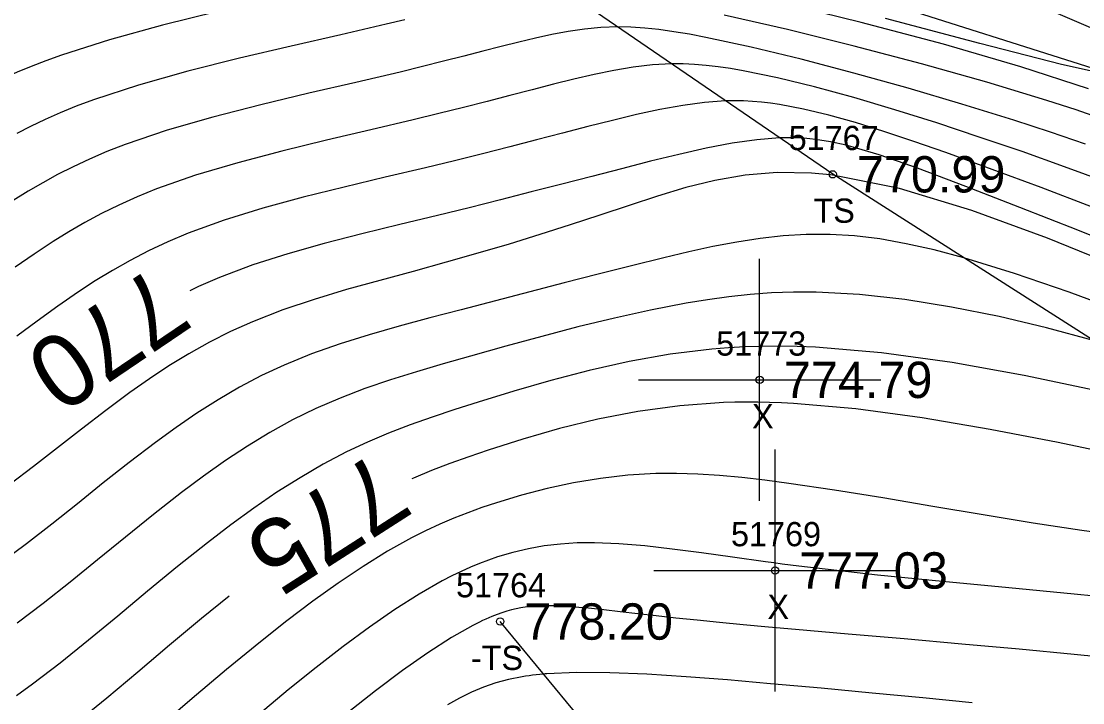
# Model space of a CAD drawing. Extents: x 1378535 to 1380697, y 997729 to 1000024.
# Drawn here: x 1379706.1 to 1379749.94, y 998840.44 to 998868.57 of the extents above; entities that cross this region are included whole.
import ezdxf

# ---------------------------------------------------------------- set-up
doc = ezdxf.new("R2010")
doc.units = 0
for name, color, linetype in [('RD_DTM_BkLn2', 7, 'Continuous'), ('RD_DTM_BkLn_txCode', 7, 'Continuous'), ('RD_DTM_Major1', 7, 'Continuous'), ('RD_DTM_Major1_Lbl', 7, 'Continuous'), ('RD_DTM_Minor1', 7, 'Continuous'), ('RD_EX_H2O', 7, 'Continuous'), ('RD_EX_Misc', 7, 'Continuous'), ('RD_EX_Misc_txCode', 7, 'Continuous'), ('RD_EX_TX_Misc_ELEV', 7, 'Continuous'), ('RD_SMD_Locator', 7, 'Continuous')]:
    doc.layers.add(name, color=color, linetype=linetype)

msp = doc.modelspace()

# ---------------------------------------------------------------- linework, layer by layer
at = {"layer": 'RD_DTM_BkLn2'}
for points in [[(1379768.924, 998848.169), (1379761.558, 998848.269), (1379739.614, 998862.253), (1379721.666, 998874.547)], [(1380321.815, 998326.615), (1380322.659, 998329.174), (1380322.261, 998332.77), (1380321.137, 998334.343), (1380320.107, 998334.637), (1380319.184, 998334.516), (1380315.041, 998338.979), (1380309.473, 998346.954), (1380304.757, 998357.874), (1380262.267, 998407.427), (1380207.067, 998458.846), (1380160.069, 998502.831), (1380114.551, 998544.043), (1380071.667, 998582.108), (1380029.128, 998620.782), (1379985.006, 998662.48), (1379936.375, 998704.347), (1379893.878, 998744.802), (1379846.871, 998787.948), (1379800.334, 998830.073), (1379753.878, 998865.5), (1379725.58, 998874.504)], [(1379855.611, 998702.628), (1379815.746, 998738.674), (1379770.168, 998788.836), (1379745.983, 998819.459), (1379725.877, 998843.791)]]:
    msp.add_lwpolyline(points, dxfattribs=at)
at = {"layer": 'RD_DTM_Major1'}
for points in [[(1379750.184, 998865.782), (1379747.386, 998866.697), (1379744.191, 998867.624), (1379740.79, 998868.526), (1379737.37, 998869.365)], [(1379714.218, 998868.979), (1379711.934, 998868.409), (1379709.745, 998867.806), (1379707.761, 998867.176), (1379707.116, 998866.943), (1379706.507, 998866.708), (1379705.931, 998866.47), (1379705.384, 998866.228), (1379704.86, 998865.983), (1379704.357, 998865.734), (1379703.744, 998865.413), (1379703.148, 998865.087), (1379702.561, 998864.756), (1379702.351, 998864.636)], [(1379752.196, 998858.954), (1379749.737, 998859.942), (1379747.344, 998860.89), (1379745.106, 998861.756), (1379743.114, 998862.501), (1379742.295, 998862.794), (1379741.537, 998863.051), (1379740.83, 998863.27), (1379740.163, 998863.451), (1379739.526, 998863.592), (1379738.907, 998863.692), (1379738.664, 998863.72), (1379738.421, 998863.741), (1379738.176, 998863.756), (1379737.928, 998863.764), (1379737.676, 998863.764), (1379737.417, 998863.758), (1379736.478, 998863.682), (1379735.464, 998863.535), (1379734.387, 998863.328), (1379733.259, 998863.076), (1379732.091, 998862.791), (1379730.895, 998862.486), (1379729.667, 998862.169), (1379728.424, 998861.848), (1379727.165, 998861.524), (1379725.891, 998861.199), (1379724.602, 998860.876), (1379723.298, 998860.556), (1379721.731, 998860.179), (1379720.163, 998859.798), (1379718.615, 998859.401), (1379717.107, 998858.977), (1379715.659, 998858.514), (1379714.29, 998858), (1379713.417, 998857.619), (1379713.063, 998857.446)], [(1379751.669, 998850.604), (1379748.929, 998851.176), (1379746.116, 998851.72), (1379743.305, 998852.198), (1379740.572, 998852.569), (1379737.992, 998852.795), (1379737.492, 998852.82), (1379737.001, 998852.837), (1379736.517, 998852.846), (1379736.04, 998852.848), (1379735.569, 998852.841), (1379735.103, 998852.827), (1379733.304, 998852.696), (1379731.572, 998852.46), (1379729.91, 998852.14), (1379728.324, 998851.755), (1379726.815, 998851.326), (1379725.389, 998850.871), (1379724.583, 998850.595), (1379723.802, 998850.313), (1379723.041, 998850.019), (1379722.296, 998849.707), (1379722.237, 998849.68)], [(1379714.682, 998844.839), (1379713.547, 998843.916), (1379712.228, 998842.812), (1379710.917, 998841.705), (1379709.631, 998840.626), (1379708.388, 998839.608), (1379707.204, 998838.685), (1379706.583, 998838.226), (1379705.98, 998837.8)]]:
    msp.add_lwpolyline(points, dxfattribs=at)
at = {"layer": 'RD_DTM_Minor1'}
for points in [[(1379750.801, 998864.523), (1379749.666, 998864.916), (1379748.453, 998865.307), (1379745.975, 998866.054), (1379743.284, 998866.81), (1379740.499, 998867.544), (1379737.741, 998868.227), (1379735.128, 998868.828)], [(1379750.059, 998863.499), (1379748.612, 998863.99), (1379747.094, 998864.483), (1379744.951, 998865.149), (1379742.728, 998865.808), (1379740.493, 998866.435), (1379738.311, 998867.009), (1379736.25, 998867.508), (1379734.375, 998867.908), (1379733.695, 998868.035), (1379733.05, 998868.141), (1379732.436, 998868.226), (1379731.848, 998868.287), (1379731.282, 998868.324), (1379730.734, 998868.336), (1379730.042, 998868.312), (1379729.364, 998868.248), (1379728.693, 998868.151), (1379728.02, 998868.024), (1379727.34, 998867.875), (1379726.644, 998867.708), (1379725.917, 998867.527), (1379725.162, 998867.334), (1379724.373, 998867.132), (1379723.545, 998866.92), (1379722.672, 998866.702), (1379721.749, 998866.477), (1379719.925, 998866.05), (1379717.984, 998865.601), (1379715.991, 998865.125), (1379714.016, 998864.617), (1379712.125, 998864.071), (1379710.385, 998863.484), (1379709.629, 998863.189), (1379708.916, 998862.883), (1379708.242, 998862.567), (1379707.6, 998862.241), (1379706.985, 998861.904), (1379706.391, 998861.558), (1379705.661, 998861.106)], [(1379721.949, 998868.636), (1379721.178, 998868.451), (1379719.302, 998868.016), (1379717.253, 998867.548), (1379715.118, 998867.044), (1379712.985, 998866.506), (1379710.943, 998865.933), (1379709.079, 998865.324), (1379708.374, 998865.06), (1379707.71, 998864.789), (1379707.083, 998864.512), (1379706.486, 998864.229), (1379705.917, 998863.939)], [(1379751.616, 998866.22), (1379749.066, 998866.791), (1379745.69, 998867.648), (1379741.801, 998868.683)], [(1379750.917, 998861.933), (1379749.189, 998862.568), (1379747.436, 998863.189), (1379745.669, 998863.793), (1379743.911, 998864.373), (1379742.175, 998864.92), (1379740.483, 998865.421), (1379738.861, 998865.865), (1379737.331, 998866.238), (1379735.917, 998866.529), (1379735.391, 998866.619), (1379734.884, 998866.692), (1379734.391, 998866.749), (1379733.909, 998866.789), (1379733.434, 998866.809), (1379732.961, 998866.81), (1379732.172, 998866.767), (1379731.378, 998866.675), (1379730.575, 998866.542), (1379729.759, 998866.374), (1379728.928, 998866.181), (1379728.078, 998865.969), (1379727.195, 998865.743), (1379726.285, 998865.507), (1379725.343, 998865.264), (1379724.365, 998865.014), (1379723.348, 998864.759), (1379722.286, 998864.5), (1379720.532, 998864.088), (1379718.708, 998863.662), (1379716.863, 998863.213), (1379715.045, 998862.734), (1379713.303, 998862.217), (1379711.687, 998861.652), (1379710.887, 998861.327), (1379710.131, 998860.986), (1379709.413, 998860.631), (1379708.726, 998860.26), (1379708.065, 998859.876), (1379707.424, 998859.478), (1379706.632, 998858.956), (1379705.854, 998858.42)], [(1379750.3, 998860.914), (1379748.227, 998861.703), (1379746.205, 998862.454), (1379744.28, 998863.149), (1379742.97, 998863.607), (1379741.731, 998864.021), (1379740.559, 998864.386), (1379739.453, 998864.697), (1379738.408, 998864.948), (1379737.421, 998865.134), (1379737.043, 998865.189), (1379736.672, 998865.233), (1379736.303, 998865.265), (1379735.935, 998865.284), (1379735.565, 998865.291), (1379735.189, 998865.284), (1379734.322, 998865.22), (1379733.417, 998865.098), (1379732.48, 998864.927), (1379731.513, 998864.717), (1379730.518, 998864.478), (1379729.501, 998864.221), (1379728.45, 998863.951), (1379727.375, 998863.673), (1379726.276, 998863.39), (1379725.148, 998863.103), (1379723.991, 998862.814), (1379722.802, 998862.525), (1379721.133, 998862.13), (1379719.434, 998861.728), (1379717.737, 998861.306), (1379716.075, 998860.855), (1379714.481, 998860.365), (1379712.989, 998859.825), (1379712.15, 998859.471), (1379711.354, 998859.096), (1379710.593, 998858.701), (1379709.862, 998858.286), (1379709.155, 998857.853), (1379708.465, 998857.401), (1379707.607, 998856.807), (1379706.761, 998856.195), (1379705.922, 998855.575)], [(1379751.642, 998858.342), (1379748.483, 998859.623), (1379745.353, 998860.764), (1379742.379, 998861.661), (1379739.689, 998862.205), (1379739.526, 998862.226), (1379739.364, 998862.245), (1379739.205, 998862.262), (1379739.046, 998862.277), (1379738.89, 998862.291), (1379738.734, 998862.302), (1379737.314, 998862.328), (1379735.993, 998862.219), (1379734.745, 998862.003), (1379733.547, 998861.703), (1379732.375, 998861.348), (1379731.203, 998860.963), (1379729.996, 998860.564), (1379728.766, 998860.165), (1379727.515, 998859.768), (1379726.245, 998859.376), (1379724.958, 998858.993), (1379723.655, 998858.622), (1379722.28, 998858.247), (1379720.903, 998857.876), (1379719.539, 998857.495), (1379718.199, 998857.092), (1379716.899, 998856.653), (1379715.651, 998856.167), (1379714.746, 998855.76), (1379713.873, 998855.319), (1379713.026, 998854.846), (1379712.201, 998854.342), (1379711.391, 998853.81), (1379710.591, 998853.249), (1379709.587, 998852.506), (1379708.588, 998851.737), (1379707.597, 998850.96), (1379706.612, 998850.192), (1379705.635, 998849.449)], [(1379751.716, 998856.527), (1379749.374, 998857.382), (1379747.124, 998858.154), (1379745.033, 998858.8), (1379743.803, 998859.129), (1379742.651, 998859.39), (1379741.562, 998859.583), (1379740.52, 998859.712), (1379739.511, 998859.775), (1379738.52, 998859.775), (1379737.568, 998859.718), (1379736.613, 998859.61), (1379735.648, 998859.458), (1379734.668, 998859.269), (1379733.666, 998859.05), (1379732.637, 998858.808), (1379731.304, 998858.481), (1379729.93, 998858.134), (1379728.527, 998857.772), (1379727.108, 998857.402), (1379724.263, 998856.658), (1379722.979, 998856.323), (1379721.715, 998855.985), (1379720.476, 998855.632), (1379719.267, 998855.254), (1379718.094, 998854.84), (1379716.96, 998854.38), (1379716.023, 998853.941), (1379715.113, 998853.463), (1379714.226, 998852.946), (1379713.355, 998852.393), (1379712.495, 998851.806), (1379711.641, 998851.186), (1379710.562, 998850.362), (1379709.487, 998849.51), (1379708.42, 998848.651), (1379707.363, 998847.805), (1379706.32, 998846.992), (1379705.296, 998846.235)], [(1379750.378, 998855.394), (1379748.444, 998855.915), (1379746.483, 998856.38), (1379744.523, 998856.773), (1379742.592, 998857.082), (1379740.719, 998857.292), (1379738.931, 998857.39), (1379737.997, 998857.392), (1379737.088, 998857.358), (1379736.199, 998857.293), (1379735.321, 998857.198), (1379734.445, 998857.077), (1379733.565, 998856.931), (1379732.092, 998856.647), (1379730.597, 998856.316), (1379729.094, 998855.95), (1379727.594, 998855.56), (1379726.111, 998855.156), (1379724.656, 998854.749), (1379723.527, 998854.429), (1379722.424, 998854.105), (1379721.346, 998853.767), (1379720.294, 998853.407), (1379719.266, 998853.015), (1379718.264, 998852.581), (1379717.307, 998852.111), (1379716.37, 998851.595), (1379715.446, 998851.035), (1379714.532, 998850.434), (1379713.622, 998849.793), (1379712.712, 998849.115), (1379711.556, 998848.211), (1379710.4, 998847.277), (1379709.252, 998846.336), (1379708.119, 998845.412), (1379707.01, 998844.532), (1379705.932, 998843.719)], [(1379750.463, 998853.326), (1379747.527, 998853.946), (1379744.542, 998854.478), (1379741.628, 998854.882), (1379738.901, 998855.114), (1379738.142, 998855.144), (1379737.406, 998855.156), (1379736.691, 998855.151), (1379735.992, 998855.128), (1379735.305, 998855.089), (1379734.628, 998855.034), (1379732.894, 998854.822), (1379731.204, 998854.525), (1379729.561, 998854.16), (1379727.97, 998853.748), (1379726.438, 998853.306), (1379724.97, 998852.852), (1379724.007, 998852.544), (1379723.073, 998852.232), (1379722.162, 998851.907), (1379721.272, 998851.564), (1379720.398, 998851.194), (1379719.536, 998850.79), (1379718.572, 998850.285), (1379717.615, 998849.729), (1379716.662, 998849.125), (1379715.709, 998848.474), (1379714.751, 998847.779), (1379713.787, 998847.042), (1379712.555, 998846.059), (1379711.318, 998845.041), (1379710.088, 998844.018), (1379708.879, 998843.017), (1379707.702, 998842.069), (1379706.57, 998841.201), (1379705.902, 998840.719)], [(1379751.443, 998847.344), (1379749.902, 998847.553), (1379747.895, 998847.856), (1379745.828, 998848.192), (1379743.744, 998848.544), (1379741.684, 998848.891), (1379739.689, 998849.214), (1379737.803, 998849.495), (1379736.808, 998849.627), (1379735.854, 998849.737), (1379734.933, 998849.821), (1379734.04, 998849.878), (1379733.167, 998849.904), (1379732.309, 998849.896), (1379731.156, 998849.829), (1379730.021, 998849.7), (1379728.907, 998849.516), (1379727.817, 998849.284), (1379726.755, 998849.008), (1379725.724, 998848.696), (1379725.128, 998848.496), (1379724.541, 998848.282), (1379723.96, 998848.053), (1379723.381, 998847.804), (1379722.802, 998847.534), (1379722.219, 998847.24), (1379721.228, 998846.689), (1379720.217, 998846.067), (1379719.187, 998845.379), (1379718.138, 998844.629), (1379717.068, 998843.82), (1379715.979, 998842.959), (1379714.577, 998841.805), (1379713.165, 998840.61), (1379711.763, 998839.413)], [(1379752.111, 998844.673), (1379749.582, 998844.925), (1379746.891, 998845.181), (1379744.146, 998845.443), (1379741.46, 998845.711), (1379738.943, 998845.989), (1379738.578, 998846.032), (1379738.22, 998846.076), (1379737.868, 998846.12), (1379737.521, 998846.164), (1379737.18, 998846.209), (1379736.844, 998846.253), (1379735.479, 998846.442), (1379734.196, 998846.622), (1379732.99, 998846.783), (1379731.856, 998846.914), (1379730.787, 998847.005), (1379729.778, 998847.044), (1379729.062, 998847.034), (1379728.372, 998846.989), (1379727.703, 998846.909), (1379727.05, 998846.794), (1379726.409, 998846.643), (1379725.775, 998846.457), (1379725.401, 998846.329), (1379725.027, 998846.188), (1379724.649, 998846.032), (1379724.268, 998845.861), (1379723.882, 998845.674), (1379723.487, 998845.47), (1379722.529, 998844.922), (1379721.525, 998844.284), (1379720.478, 998843.561), (1379719.393, 998842.762), (1379718.274, 998841.894), (1379717.124, 998840.965), (1379715.636, 998839.719)], [(1379751.684, 998842.219), (1379749.589, 998842.434), (1379747.317, 998842.649), (1379744.949, 998842.862), (1379742.565, 998843.07), (1379740.247, 998843.271), (1379738.075, 998843.461), (1379736.965, 998843.561), (1379735.92, 998843.658), (1379734.937, 998843.751), (1379734.012, 998843.843), (1379733.141, 998843.934), (1379732.321, 998844.023), (1379731.559, 998844.111), (1379730.84, 998844.194), (1379730.163, 998844.271), (1379729.527, 998844.337), (1379728.929, 998844.39), (1379728.368, 998844.425), (1379728.081, 998844.436), (1379727.802, 998844.439), (1379727.53, 998844.433), (1379727.262, 998844.418), (1379726.997, 998844.391), (1379726.734, 998844.352), (1379726.542, 998844.315), (1379726.348, 998844.27), (1379726.153, 998844.217), (1379725.954, 998844.155), (1379725.75, 998844.083), (1379725.542, 998844.002), (1379725.416, 998843.949), (1379725.287, 998843.893), (1379725.156, 998843.833), (1379725.023, 998843.769), (1379724.887, 998843.701), (1379724.748, 998843.629), (1379723.869, 998843.127), (1379722.898, 998842.501), (1379721.848, 998841.763), (1379720.731, 998840.927), (1379719.558, 998840.004)], [(1379745.371, 998840.429), (1379743.33, 998840.634), (1379741.241, 998840.837), (1379739.135, 998841.035), (1379737.044, 998841.225), (1379735.271, 998841.379), (1379733.559, 998841.513), (1379731.931, 998841.617), (1379730.413, 998841.679), (1379729.029, 998841.689), (1379727.803, 998841.634), (1379727.78, 998841.632), (1379727.758, 998841.63), (1379727.736, 998841.628), (1379727.691, 998841.624), (1379727.669, 998841.623), (1379727.515, 998841.608), (1379727.364, 998841.592), (1379727.216, 998841.574), (1379727.071, 998841.555), (1379726.929, 998841.534), (1379726.79, 998841.511), (1379726.229, 998841.398), (1379725.698, 998841.255), (1379725.189, 998841.079), (1379724.693, 998840.87), (1379724.199, 998840.626), (1379723.701, 998840.345)]]:
    msp.add_lwpolyline(points, dxfattribs=at)
at = {"layer": 'RD_EX_H2O'}
msp.add_lwpolyline([(1379736.894, 998874.065), (1379751.828, 998867.642), (1379771.891, 998856.367), (1379801.405, 998830.336), (1379847.091, 998789.131), (1379893.404, 998746.574), (1379936.347, 998705.935), (1379983.745, 998664.271), (1380032.204, 998621.669), (1380073.465, 998582.905), (1380116.04, 998544.611), (1380160.954, 998503.902), (1380207.715, 998459.994), (1380261.249, 998409.341)], dxfattribs=at)
at = {"layer": 'RD_EX_Misc'}
for p, q in [((1379736.597, 998848.768), (1379736.597, 998858.768)), ((1379731.597, 998853.768), (1379741.597, 998853.768)), ((1379737.232, 998840.899), (1379737.232, 998850.899)), ((1379732.232, 998845.899), (1379742.232, 998845.899))]:
    msp.add_line(p, q, dxfattribs=at)
at = {"layer": 'RD_SMD_Locator'}
for centre in [(1379739.614, 998862.253), (1379736.597, 998853.768), (1379737.232, 998845.899), (1379725.877, 998843.791)]:
    msp.add_circle(centre, 0.15, dxfattribs=at)

# ---------------------------------------------------------------- texts
at = {"layer": 'RD_DTM_BkLn_txCode'}
for s, p in [('51767', (1379737.795, 998863.253)), ('TS', (1379738.819, 998860.253)), ('51764', (1379724.058, 998844.791)), ('-TS', (1379724.672, 998841.791))]:
    msp.add_text(s, height=1, dxfattribs=at).set_placement(p)
at = {"layer": 'RD_DTM_Major1_Lbl'}
for s, rotation, p in [('770', 214.0889, (1379711.608, 998858.543)), ('775', 212.6523, (1379720.776, 998850.873))]:
    msp.add_text(s, height=3, rotation=rotation, dxfattribs=at).set_placement(p)
at = {"layer": 'RD_EX_Misc_txCode'}
for s, p in [('51773', (1379734.802, 998854.768)), ('X', (1379736.282, 998851.768)), ('51769', (1379735.413, 998846.899)), ('X', (1379736.917, 998843.899))]:
    msp.add_text(s, height=1, dxfattribs=at).set_placement(p)
at = {"layer": 'RD_EX_TX_Misc_ELEV'}
for s, p in [('770.99', (1379740.614, 998861.503)), ('774.79', (1379737.597, 998853.018)), ('777.03', (1379738.232, 998845.149)), ('778.20', (1379726.877, 998843.041))]:
    msp.add_text(s, height=1.5, dxfattribs=at).set_placement(p)

doc.saveas('drawing.dxf')
